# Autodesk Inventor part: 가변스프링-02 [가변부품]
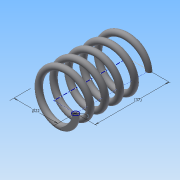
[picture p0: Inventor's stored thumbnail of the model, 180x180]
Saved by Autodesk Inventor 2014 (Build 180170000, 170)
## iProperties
Created: 2015-09
Part Number: 가변스프링-02 [가변부품]
Material: 강철, 탄소
Document SubType Name: Modeling
Designer: study
Density: 7.87 g/cm^3
Appearance: 반연마
Mass: 18.6365 g
Surface Area: 32.4155 cm^2
Volume: 2.36804 cm^3
Author: study
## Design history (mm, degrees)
sketch "스케치1"
  geometry: L1 (0, 0)-(11, 0); L2 (11, 0)-(11, 25.208); L3 (11, 25.208)-(0, 25.208); L4 (0, 25.208)-(0, 0); C1 r 1.5 at (11, 0)
  constraints: 8 end point, 2 parallel, 1 centre point, 1 coincident, 1 horizontal, 1 perpendicular
  dimensions: "d0" = 22 diameter of L2 L4; "d1" = 3 diameter of C1; "d2" = 25.20829 distance between parallel lines of L1 L3 (derived)
feature "코일1" sketch "스케치1" pitch "d3" = 10; turns "d5" = 5; dims "d4" = 25.20829 (= d2), "d6" = 0, angle "d7" = 90 deg, angle "d8" = 90 deg, "d9" = 0, "d10" = 0
node "작업 평면1"
sketch "스케치2"
  geometry: L1 (-12.5, 0)-(-9.5, 0) reference; 1 further point
  constraints: 1 horizontal alignment
extrude "돌출1" cut sketch "스케치2" distance "d12" = 10; taper "d13" = 0 deg
node "작업 평면2"
sketch "스케치3"
  geometry: L1 (-9.5, 0)-(-12.5, 0) reference; 1 further point
  constraints: 1 horizontal alignment
extrude "돌출2" cut sketch "스케치3" distance "d15" = 10; taper "d16" = 0 deg
node "솔리드1"
node "절단 모서리 투영1"
node "절단 모서리 투영2"
other parameters: "d11" = 0, "d14" = 25.20829 (= d2)
